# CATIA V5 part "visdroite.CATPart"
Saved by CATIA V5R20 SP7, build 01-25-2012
Part number: vis droite
Publications: "Face", "Face1", "Arête", "Corps principal", "Point.1"
Bounding box of the stored display mesh (mm): x 7.86 to 16.96, y 18.5 to 27.5, z -12.221 to 1.779
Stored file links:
  F:\Travaux\Modélisations\CFAO_2011\CFAO_2011_MMS\CFAO_2011_MMS_DONE\CFAO_2011_MMS_jboiteux\Catia\visdroite.CATPart
  U:\finthinkmotion\stepper.CATProduct
  F:\Travaux\Modélisations\CFAO_2011\CFAO_2011_MMS\CFAO_2011_MMS_DONE\CFAO_2011_MMS_jboiteux\Catia\bati.CATPart
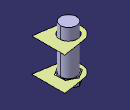
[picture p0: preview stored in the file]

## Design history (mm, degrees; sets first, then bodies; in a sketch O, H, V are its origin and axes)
Parameters
  rayontube = 9 mm {= External.royontubebati}
External parameters (linked from other documents)
  External.royontubebati = 9 mm
Set1
  DatumSurface1: linked copy from another document
  Point1: linked copy from another document
  DatumCurve1: linked copy from another document
  DatumSurface2: linked copy from another document
Body1 (main body)
  Sketch1 on face of DatumSurface1, origin (0, 0, -10.2209), H (1, 0, 0), V (0, -1, 0)
    projected circle E1 centre (11.46, -23) radius 2.15 from edge of DatumCurve1
  Pad1: profile Sketch1, direction (0, 0, 1), up to face of DatumSurface2, offset 3 {= rayontube /3}
  Sketch2 on start face of Pad1, origin (0, 0, -10.2209), H (1, 0, 0), V (0, -1, 0)
    point P1 (11.46, -23)
    point P2 (13.8268, -24.5115)
    point P3 (13.9524, -21.7061)
    point P4 (11.5856, -20.1946)
    point P5 (9.0932, -21.4885)
    point P6 (8.9676, -24.2939)
    point P7 (11.3344, -25.8054)
    point P8 (13.8896, -23.1088)
    line L1 (13.8268, -24.5115) -> (13.9524, -21.7061)
    line L2 (13.9524, -21.7061) -> (11.5856, -20.1946)
    line L3 (11.5856, -20.1946) -> (9.0932, -21.4885)
    line L4 (9.0932, -21.4885) -> (8.9676, -24.2939)
    line L5 (8.9676, -24.2939) -> (11.3344, -25.8054)
    line L6 (11.3344, -25.8054) -> (13.8268, -24.5115)
    construction line L7 (11.46, -23) -> (13.8896, -23.1088)
    construction circle A1 centre (11.46, -23) radius 2.8082
    construction arc A2 centre (8.9676, -24.2939) radius 2.8082 from (9.0932, -21.4885) to (11.3344, -25.8054) cw
    construction arc A3 centre (13.9524, -21.7061) radius 2.8082 from (11.5856, -20.1946) to (13.8268, -24.5115) ccw
    reference projected point E1 (11.46, -23) from Point1
    reference projected point E2 (11.46, -23) from Point1
    distance E2 L6 = 2.432 {= rayontube *304/1125}
    coincidence: A1 P2, A1 P3, A1 P4, A1 P5, A1 P6, A1 P7, A2 P1, A3 P1, E1 P1
    midpoint: P8 L1
    parallelism: L1 L4
  Pad2: profile Sketch2, direction (0, 0, -1), length 2 {= rayontube /9*2}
